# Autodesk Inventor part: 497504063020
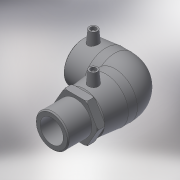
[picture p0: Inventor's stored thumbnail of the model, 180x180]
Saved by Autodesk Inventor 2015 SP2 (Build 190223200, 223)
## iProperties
Created: 2017-06
Part Number: 497504063020
Material: Generic
Description: PE Male Transition Elbow 90° 63x  1 1_2
Document SubType Name: Modeling
Designer: KIM
Mass: 662.373 g
Surface Area: 1088.56 cm^2
Volume: 662.373 cm^3
Density: 1 g/cm^3
Appearance: Default
Author: KIM
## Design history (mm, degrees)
derived "497504.ipt"
feature "Solid1::497504.ipt"
feature "Solid2::497504.ipt"
tag "TaggingFeature1"
workplane "Work Plane2"
body "Solid1"
body "Solid2"
other parameters: "d2" = 81, "d4" = 40.66667, "d5" = 72.9, "d8" = 168 deg, "d10" = 22.8, "d11" = 7.6, "d29" = 59, "d30" = 15, "d31" = 63.44, "d34" = 5 deg, "d41" = 4, "d42" = 14, "d43" = 0, "d48" = 81.5, "d49" = 63, "d50" = 6.3, "d51" = 22.8, "d52" = 57, "d54" = 90 deg, "d86" = 3, "d87" = 0, "d93" = 0.1, "d94" = 14.25, "d95" = 59.614, "d96" = 41.7298, "d97" = 48, "d98" = 57, "d99" = 81, "d100" = 51.3, "d102" = 1.89, "d106" = 0, "d108" = 51.3, "d114" = 57, "d115" = 0, "d116" = -57, "d_" = 63, "L_" = 179, "L_1" = 57, "D_" = 48, "A_" = 59, "d_2" = 12, "L_2" = 57, "D_1" = 81, "R_" = 59.614
